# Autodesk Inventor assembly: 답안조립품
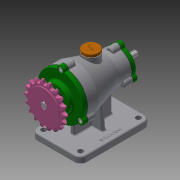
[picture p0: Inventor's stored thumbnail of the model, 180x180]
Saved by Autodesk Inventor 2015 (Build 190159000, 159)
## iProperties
Created: 2020-03
Part Number: 답안조립품
Document SubType Name: Assembly
Designer: Administrator
Author: Administrator
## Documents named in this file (15)
- C:\Users\Administrator\Desktop\700306V1007\답안조립품.iam
- C:\Users\Administrator\Desktop\700306V1007\본체.ipt
- C:\Users\Administrator\Desktop\700306V1007\뒤커버.ipt
- C:\Users\Administrator\Desktop\700306V1007\앞커버.ipt
- C:\Users\Administrator\Desktop\700306V1007\개스킷 A.ipt
- C:\Users\Administrator\Desktop\700306V1007\개스킷 B.ipt
- C:\Users\Administrator\Desktop\700306V1007\베어링 6200.ipt
- C:\Users\Administrator\Desktop\700306V1007\베어링 6203.ipt
- C:\Users\Administrator\Desktop\700306V1007\오일 실 10 20 7.ipt
- C:\Users\Administrator\Desktop\700306V1007\오일 실 17 30 8.ipt
- C:\Users\Administrator\Desktop\700306V1007\축.ipt
- C:\Users\Administrator\Desktop\700306V1007\마개.ipt
- C:\Users\Administrator\Desktop\700306V1007\볼트 M5.ipt
- C:\Users\Administrator\Desktop\700306V1007\스프로킷.ipt
- C:\Users\Administrator\Desktop\700306V1007\키 4x4x14.ipt
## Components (2 placed, 2 different names)
1. 개스킷 A:1
2. 개스킷 B:1
